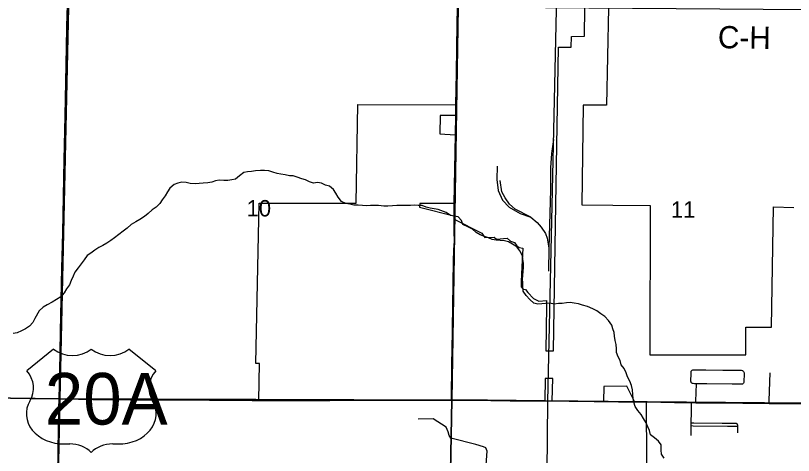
# Model space of a CAD drawing. Extents: x 0 to 42, y 0 to 22.
# Drawn here: x 3.119 to 5.107, y 17.347 to 18.47 of the extents above; entities that cross this region are included whole.
import ezdxf

# ---------------------------------------------------------------- set-up
doc = ezdxf.new("R2010")
doc.units = 0
for name, color, linetype in [('GM_X_City_Street', 7, 'Continuous'), ('GM_X_Corporation', 7, 'Continuous'), ('GM_X_County_Road_Text', 7, 'Continuous'), ('GM_X_Minor_River', 7, 'Continuous'), ('GM_X_Rail_Line', 7, 'Continuous'), ('GM_X_Section', 7, 'Continuous'), ('GM_X_Section_Text', 7, 'Continuous'), ('GM_X_State_Route', 7, 'Continuous'), ('GM_X_Township_Road', 7, 'Continuous'), ('GM_X_US_Location', 7, 'Continuous'), ('GM_X_US_Route', 7, 'Continuous'), ('GM_X_US_Shield', 7, 'Continuous')]:
    doc.layers.add(name, color=color, linetype=linetype)

msp = doc.modelspace()

# ---------------------------------------------------------------- linework, layer by layer
at = {"layer": 'GM_X_City_Street'}
msp.add_line((4.8455, 17.3982), (4.8458, 17.4229), dxfattribs=at)
for points in [[(4.8593, 17.5296), (4.8536, 17.5299), (4.8503, 17.5305), (4.8488, 17.5309), (4.8475, 17.5315), (4.8465, 17.5323), (4.8458, 17.5333), (4.8453, 17.5345), (4.845, 17.5356), (4.8448, 17.5373), (4.8448, 17.5403), (4.8451, 17.5529), (4.8453, 17.559), (4.8455, 17.5605), (4.8459, 17.5619), (4.8464, 17.563), (4.8472, 17.5641), (4.8481, 17.5648), (4.8494, 17.5654), (4.8521, 17.5658), (4.8832, 17.5655), (4.9265, 17.5649), (4.9606, 17.5647), (4.9699, 17.5648), (4.9729, 17.5646), (4.9755, 17.5641), (4.9767, 17.5636), (4.9777, 17.5629), (4.9796, 17.5608), (4.9801, 17.5596), (4.9805, 17.5582), (4.9807, 17.5551), (4.9802, 17.535), (4.98, 17.5334), (4.9799, 17.5327), (4.9795, 17.5314), (4.9785, 17.5304), (4.9778, 17.5297), (4.9763, 17.5291), (4.975, 17.5289), (4.972, 17.5288), (4.9503, 17.5289), (4.8854, 17.5294), (4.8593, 17.5296)], [(5.0448, 17.4797), (5.045, 17.4869), (5.0473, 17.558)], [(4.8575, 17.4816), (4.8576, 17.4856), (4.8593, 17.5296)], [(4.8458, 17.4305), (4.846, 17.4578), (4.8462, 17.4763), (4.8463, 17.4818)], [(4.8458, 17.4305), (4.8525, 17.4304), (4.9243, 17.4296), (4.9586, 17.4295), (4.9595, 17.4294), (4.9602, 17.4292), (4.9609, 17.4289), (4.9615, 17.4285), (4.9621, 17.428), (4.9626, 17.4274), (4.963, 17.4267), (4.9633, 17.4261), (4.9635, 17.4253), (4.9637, 17.4245), (4.9638, 17.423), (4.9637, 17.4217)], [(4.8458, 17.4229), (4.8458, 17.4238), (4.8458, 17.4305)], [(4.8458, 17.4229), (4.8505, 17.4228), (4.9387, 17.4217), (4.9576, 17.4217), (4.9637, 17.4217)], [(4.9637, 17.4217), (4.9637, 17.4199), (4.9635, 17.4043)]]:
    msp.add_lwpolyline(points, dxfattribs=at)
at = {"layer": 'GM_X_Corporation'}
for points in [[(4.7322, 17.3283), (4.7317, 17.4841), (4.7007, 17.4842), (4.6813, 17.5236), (4.622, 17.5231), (4.6212, 17.485), (4.4905, 17.4864), (4.4918, 17.5431), (4.4726, 17.5435), (4.4714, 17.4866), (4.325, 17.4882), (4.2327, 17.4882), (4.1997, 17.4884), (3.7408, 17.4875), (3.7425, 17.5818), (3.7332, 17.5818), (3.7415, 17.9914), (3.9899, 17.9908), (3.9942, 18.2426), (4.2442, 18.2422), (4.2437, 18.2145), (4.2039, 18.2146), (4.2031, 18.1684), (4.2429, 18.1658), (4.2401, 17.9902), (4.152, 17.9904), (4.1518, 17.9809), (4.2388, 17.9586), (4.2396, 17.9586), (4.2396, 17.9501), (4.3108, 17.9146), (4.316, 17.9065), (4.3186, 17.9034), (4.3426, 17.9044), (4.3478, 17.8987), (4.3753, 17.902), (4.3841, 17.8943), (4.3943, 17.8904), (4.4002, 17.8818), (4.4059, 17.8776), (4.4151, 17.8757), (4.413, 17.8286), (4.4113, 17.7907), (4.4109, 17.7771), (4.4163, 17.7712), (4.4222, 17.7705), (4.4286, 17.7633), (4.443, 17.7477), (4.4564, 17.7409), (4.4762, 17.7426), (4.4758, 17.7279), (4.4738, 17.6142), (4.4935, 17.6139), (4.4996, 17.9873), (4.5064, 18.3896), (4.5393, 18.3896), (4.5398, 18.4169), (4.5728, 18.4172), (4.5741, 18.4897)], [(4.6347, 18.4893), (4.6294, 18.2409), (4.5695, 18.2409), (4.5662, 17.9866), (4.6454, 17.9857), (4.7405, 17.9846), (4.7396, 17.6036), (4.9854, 17.6038), (4.9854, 17.6743), (5.0509, 17.6744), (5.056, 17.982), (5.1081, 17.9802)]]:
    msp.add_lwpolyline(points, dxfattribs=at)
at = {"layer": 'GM_X_Minor_River'}
for points in [[(4.1683, 17.9807), (4.1578, 17.9851), (4.1483, 17.9854), (4.1385, 17.9856), (4.1282, 17.9847), (4.1161, 17.9853), (4.1039, 17.9852), (4.0933, 17.9854), (4.0823, 17.9842), (4.0709, 17.9837), (4.0603, 17.9831), (4.047, 17.9846), (4.0368, 17.9848), (4.0265, 17.9847), (4.017, 17.9845), (4.0057, 17.9847), (3.9943, 17.9858), (3.9833, 17.9856), (3.9731, 17.9881), (3.9629, 17.9903), (3.952, 17.9954), (3.9436, 18.0059), (3.9377, 18.0162), (3.9315, 18.0263), (3.9211, 18.0348), (3.9113, 18.0373), (3.9008, 18.0417), (3.8906, 18.0435), (3.8803, 18.0422), (3.8701, 18.0451), (3.8604, 18.0506), (3.8506, 18.0531), (3.8389, 18.0572), (3.8288, 18.0604), (3.8193, 18.0606), (3.8083, 18.0632), (3.7974, 18.0649), (3.7875, 18.0667), (3.777, 18.0703), (3.7661, 18.0732), (3.7551, 18.0746), (3.7449, 18.0745), (3.7323, 18.0736), (3.722, 18.0719), (3.7118, 18.0706), (3.7022, 18.0693), (3.6914, 18.0605), (3.6817, 18.0523), (3.6718, 18.0507), (3.6619, 18.049), (3.6513, 18.0492), (3.6396, 18.0499), (3.63, 18.0482), (3.6205, 18.045), (3.6106, 18.0429), (3.5984, 18.042), (3.5779, 18.0402), (3.5658, 18.0413), (3.5556, 18.0441), (3.5442, 18.0448), (3.5343, 18.0423), (3.5247, 18.0384), (3.5139, 18.0295), (3.5076, 18.0198), (3.5017, 18.01), (3.4942, 17.9996), (3.4883, 17.9898), (3.4786, 17.9806), (3.4682, 17.974), (3.4585, 17.9647), (3.4488, 17.9573), (3.4369, 17.9489), (3.4265, 17.943), (3.415, 17.9364), (3.4041, 17.9272), (3.3941, 17.9191), (3.3836, 17.9106), (3.3724, 17.9025), (3.3628, 17.8955), (3.3524, 17.8889), (3.342, 17.883), (3.332, 17.8776), (3.322, 17.871), (3.3119, 17.8636), (3.3023, 17.857), (3.2945, 17.8465), (3.287, 17.8364), (3.2796, 17.8256), (3.271, 17.8148), (3.2666, 17.805), (3.2614, 17.7937), (3.2569, 17.7824), (3.2499, 17.772), (3.2439, 17.7619), (3.2354, 17.7522), (3.2242, 17.7452), (3.213, 17.7386), (3.2, 17.7313), (3.1896, 17.7255), (3.1799, 17.7158), (3.1688, 17.6964)], [(4.7763, 17.3397), (4.7693, 17.3501), (4.7688, 17.36), (4.7687, 17.3737), (4.7618, 17.3833), (4.7521, 17.3915), (4.742, 17.3997), (4.7393, 17.4104), (4.7349, 17.42), (4.7302, 17.4303), (4.7233, 17.4415), (4.7178, 17.4515), (4.7093, 17.4615), (4.7028, 17.4719), (4.6992, 17.4826), (4.6975, 17.4925), (4.6966, 17.5021), (4.6954, 17.5142), (4.693, 17.5253), (4.6887, 17.5368), (4.6829, 17.5479), (4.6797, 17.5582), (4.6747, 17.569), (4.6669, 17.5786), (4.6641, 17.5889), (4.6587, 17.5985), (4.6547, 17.6093), (4.6546, 17.6188), (4.6541, 17.6302), (4.6513, 17.6401), (4.6497, 17.6511), (4.6484, 17.6606), (4.6455, 17.6702), (4.6424, 17.6798), (4.6339, 17.691), (4.6247, 17.7018), (4.6149, 17.7081), (4.6049, 17.7159), (4.594, 17.7211), (4.5809, 17.7271), (4.5677, 17.7308), (4.5575, 17.7337), (4.5469, 17.7354), (4.5367, 17.7372), (4.5268, 17.7362), (4.5162, 17.735), (4.5063, 17.7348), (4.4957, 17.7335), (4.4847, 17.7357), (4.4737, 17.7352), (4.4642, 17.7342), (4.4539, 17.7333), (4.4433, 17.7358), (4.4329, 17.7448), (4.4241, 17.7549), (4.4164, 17.7664), (4.4151, 17.7763), (4.415, 17.7873), (4.4148, 17.7968), (4.415, 17.8063), (4.4164, 17.8161), (4.4174, 17.8279), (4.4169, 17.8374), (4.4152, 17.8473), (4.4143, 17.8568), (4.4074, 17.8695), (4.4001, 17.8795), (4.3892, 17.8866), (4.3787, 17.8925), (4.3689, 17.895), (4.3579, 17.8956), (4.3473, 17.8966), (4.3371, 17.8984), (4.3274, 17.9028), (4.3176, 17.9057), (4.3067, 17.9101), (4.2966, 17.9164), (4.2865, 17.9242), (4.2745, 17.9309), (4.2625, 17.9369), (4.2586, 17.9465), (4.2505, 17.9565), (4.2403, 17.9579), (4.2304, 17.9592), (4.2196, 17.9674), (4.1993, 17.9747), (4.1891, 17.9761), (4.1785, 17.9786), (4.1683, 17.9807)], [(3.1688, 17.6964), (3.1636, 17.6866), (3.1554, 17.6769), (3.1447, 17.6703), (3.1343, 17.6652), (3.1232, 17.6602), (3.1133, 17.6581)], [(4.3197, 17.2987), (4.3245, 17.3574), (4.3213, 17.3662), (4.3149, 17.369), (4.2953, 17.3748), (4.2312, 17.391), (4.2268, 17.3975), (4.2247, 17.4075), (4.2193, 17.4194), (4.1864, 17.4402), (4.1477, 17.4395)]]:
    msp.add_lwpolyline(points, dxfattribs=at)
at = {"layer": 'GM_X_Rail_Line'}
msp.add_line((4.4821, 17.876), (4.4806, 17.8171), dxfattribs=at)
for points in [[(4.4201, 14.1), (4.4258, 14.4841), (4.4505, 15.4825), (4.4609, 16.2603), (4.4628, 16.4862), (4.4739, 16.927), (4.4741, 16.9438), (4.4795, 17.4845), (4.5072, 18.7551), (4.5183, 19.5978), (4.5387, 20.5461), (4.5449, 20.9)], [(4.4941, 18.1539), (4.4888, 18.1178), (4.4863, 18.0816), (4.486, 18.0251), (4.4821, 17.876)], [(4.3496, 18.0855), (4.3487, 18.0514), (4.3525, 18.0231), (4.3638, 17.999), (4.3808, 17.9806), (4.4089, 17.9644), (4.4358, 17.9554)], [(4.4358, 17.9554), (4.3958, 17.976), (4.3815, 17.9886), (4.3707, 18.0047), (4.362, 18.0199), (4.3573, 18.0488)], [(4.4358, 17.9554), (4.4522, 17.9419), (4.4625, 17.9295), (4.4736, 17.9133), (4.478, 17.9016), (4.4821, 17.876)]]:
    msp.add_lwpolyline(points, dxfattribs=at)
at = {"layer": 'GM_X_Section'}
for points in [[(2.2423, 18.509), (3.2549, 18.4906), (3.2323, 17.4917), (2.2245, 17.5054)], [(3.2549, 18.4906), (4.2501, 18.4923), (4.2338, 17.4876), (3.2323, 17.4917)], [(4.2501, 18.4923), (5.2524, 18.4847), (5.2334, 17.4797), (4.2338, 17.4876)], [(3.2323, 17.4917), (3.2111, 16.4878), (2.2056, 16.5033), (2.2245, 17.5054)], [(4.2338, 17.4876), (4.2153, 16.4855), (3.2111, 16.4878), (3.2323, 17.4917)], [(5.2334, 17.4797), (5.2156, 16.4769), (4.2153, 16.4855), (4.2338, 17.4876)]]:
    msp.add_lwpolyline(points, close=True, dxfattribs=at)
at = {"layer": 'GM_X_State_Route'}
for p, q in [((4.2439, 18.2145), (4.2444, 18.2416)), ((4.2431, 18.1655), (4.2439, 18.2145)), ((4.2404, 17.9901), (4.2431, 18.1655)), ((4.2398, 17.9581), (4.2404, 17.9901)), ((4.2397, 17.95), (4.2398, 17.9581)), ((4.4721, 17.486), (4.4907, 17.4859)), ((4.701, 17.4837), (4.7319, 17.4836)), ((4.7319, 17.4836), (4.8025, 17.4824)), ((4.8463, 17.4818), (4.8575, 17.4816))]:
    msp.add_line(p, q, dxfattribs=at)
for points in [[(4.2444, 18.2416), (4.2457, 18.3238), (4.2478, 18.4479), (4.2485, 18.4908)], [(4.233, 17.4876), (4.2342, 17.5854), (4.2346, 17.6134), (4.2381, 17.843), (4.2388, 17.8711), (4.2399, 17.8835), (4.2409, 17.8927), (4.2412, 17.9044), (4.2403, 17.9074), (4.2396, 17.9169), (4.2396, 17.945), (4.2397, 17.95)], [(3.0614, 17.4943), (3.0934, 17.4938), (3.1555, 17.4924), (3.2306, 17.4912)], [(3.2306, 17.4912), (3.2424, 17.4911), (3.317, 17.4901), (3.4132, 17.489), (3.6151, 17.4876), (3.7238, 17.4869), (3.7409, 17.487)], [(3.7409, 17.487), (3.9226, 17.4873), (4.0655, 17.4878), (4.1214, 17.4881), (4.2145, 17.4878), (4.233, 17.4876)], [(4.233, 17.4876), (4.3236, 17.4877), (4.3246, 17.4876), (4.3827, 17.4867), (4.3928, 17.4866)], [(4.3928, 17.4866), (4.4574, 17.4862), (4.4721, 17.486)], [(4.4907, 17.4859), (4.5414, 17.4852), (4.5974, 17.4848), (4.6214, 17.4845)], [(4.6214, 17.4845), (4.6596, 17.484), (4.701, 17.4837)], [(4.8025, 17.4824), (4.8166, 17.4822), (4.8463, 17.4818)], [(4.8575, 17.4816), (4.9098, 17.4809), (5.0448, 17.4797)], [(5.0448, 17.4797), (5.0465, 17.4797), (5.1055, 17.4791), (5.1925, 17.4778), (5.2204, 17.4775), (5.2334, 17.4776)]]:
    msp.add_lwpolyline(points, dxfattribs=at)
at = {"layer": 'GM_X_Township_Road'}
for points in [[(3.2306, 17.4912), (3.2321, 17.5609), (3.2344, 17.6634), (3.238, 17.8251), (3.2401, 17.9152), (3.2428, 18.0551), (3.2439, 18.1017), (3.2459, 18.2136), (3.2486, 18.3441), (3.2495, 18.3908), (3.2505, 18.4374), (3.2511, 18.4747), (3.2517, 18.492)], [(3.2134, 16.4891), (3.2159, 16.6283), (3.2177, 16.7371), (3.2195, 16.8211), (3.2214, 16.933), (3.2241, 17.0853), (3.2249, 17.1381), (3.2265, 17.2407), (3.2275, 17.2998), (3.2292, 17.4148), (3.2301, 17.4677), (3.2306, 17.4912)]]:
    msp.add_lwpolyline(points, dxfattribs=at)
at = {"layer": 'GM_X_US_Route'}
for p, q in [((4.4721, 17.486), (4.4907, 17.4859)), ((4.701, 17.4837), (4.7319, 17.4836)), ((4.7319, 17.4836), (4.8025, 17.4824)), ((4.8463, 17.4818), (4.8575, 17.4816))]:
    msp.add_line(p, q, dxfattribs=at)
for points in [[(3.0614, 17.4943), (3.0934, 17.4938), (3.1555, 17.4924), (3.2306, 17.4912)], [(3.2306, 17.4912), (3.2424, 17.4911), (3.317, 17.4901), (3.4132, 17.489), (3.6151, 17.4876), (3.7238, 17.4869), (3.7409, 17.487)], [(3.7409, 17.487), (3.9226, 17.4873), (4.0655, 17.4878), (4.1214, 17.4881), (4.2145, 17.4878), (4.233, 17.4876)], [(4.233, 17.4876), (4.3236, 17.4877), (4.3246, 17.4876), (4.3827, 17.4867), (4.3928, 17.4866)], [(4.3928, 17.4866), (4.4574, 17.4862), (4.4721, 17.486)], [(4.4907, 17.4859), (4.5414, 17.4852), (4.5974, 17.4848), (4.6214, 17.4845)], [(4.6214, 17.4845), (4.6596, 17.484), (4.701, 17.4837)], [(4.8025, 17.4824), (4.8166, 17.4822), (4.8463, 17.4818)], [(4.8575, 17.4816), (4.9098, 17.4809), (5.0448, 17.4797)], [(5.0448, 17.4797), (5.0465, 17.4797), (5.1055, 17.4791), (5.1925, 17.4778), (5.2204, 17.4775), (5.2334, 17.4776)]]:
    msp.add_lwpolyline(points, dxfattribs=at)
at = {"layer": 'GM_X_US_Shield'}
for p, q in [((3.2166, 17.6179), (3.1479, 17.563)), ((3.4775, 17.563), (3.4088, 17.6179)), ((3.244, 17.3763), (3.2578, 17.3763)), ((3.3676, 17.3763), (3.3814, 17.3763))]:
    msp.add_line(p, q, dxfattribs=at)
for centre, major_axis, start_param, end_param in [((3.2646, 17.6572), (-0.0687, 0), 0.795399, 2.346194), ((3.3608, 17.6572), (-0.0687, 0), 0.795399, 2.346194), ((3.0692, 17.5189), (0.0961, 0), 5.838949, 6.894067), ((3.5562, 17.5189), (-0.0961, 0), 5.672304, 6.727422), ((3.243, 17.4531), (0.0961, 0), 2.702327, 4.723529), ((3.3824, 17.4531), (-0.0961, 0), 1.559657, 3.580859), ((3.2578, 17.3213), (-0.0687, 0), 3.785094, 4.712389), ((3.3676, 17.3213), (-0.0687, 0), 4.712389, 5.639684)]:
    msp.add_ellipse(centre, major_axis=major_axis, ratio=0.8, start_param=start_param, end_param=end_param, dxfattribs=at)

# ---------------------------------------------------------------- texts
at = {"layer": 'GM_X_County_Road_Text'}
msp.add_text('C-H', height=0.05682, rotation=359.2083, dxfattribs=at).set_placement((4.9135, 18.3867))
at = {"layer": 'GM_X_Section_Text'}
for s, p in [('10', (3.7099, 17.9571)), ('11', (4.7937, 17.9537))]:
    msp.add_text(s, height=0.04186, rotation=0, dxfattribs=at).set_placement(p)
at = {"layer": 'GM_X_US_Location'}
for s in ['0', '/']:
    msp.add_text(s, height=0.000189, dxfattribs=at).set_placement((3.3128, 17.4915))
msp.add_text('20A', height=0.000189, rotation=0, dxfattribs=at).set_placement((3.2487, 17.4523))
at = {"layer": 'GM_X_US_Shield'}
msp.add_text('20A', height=0.13184, dxfattribs=at).set_placement((3.1942, 17.4257))

doc.saveas('drawing.dxf')
